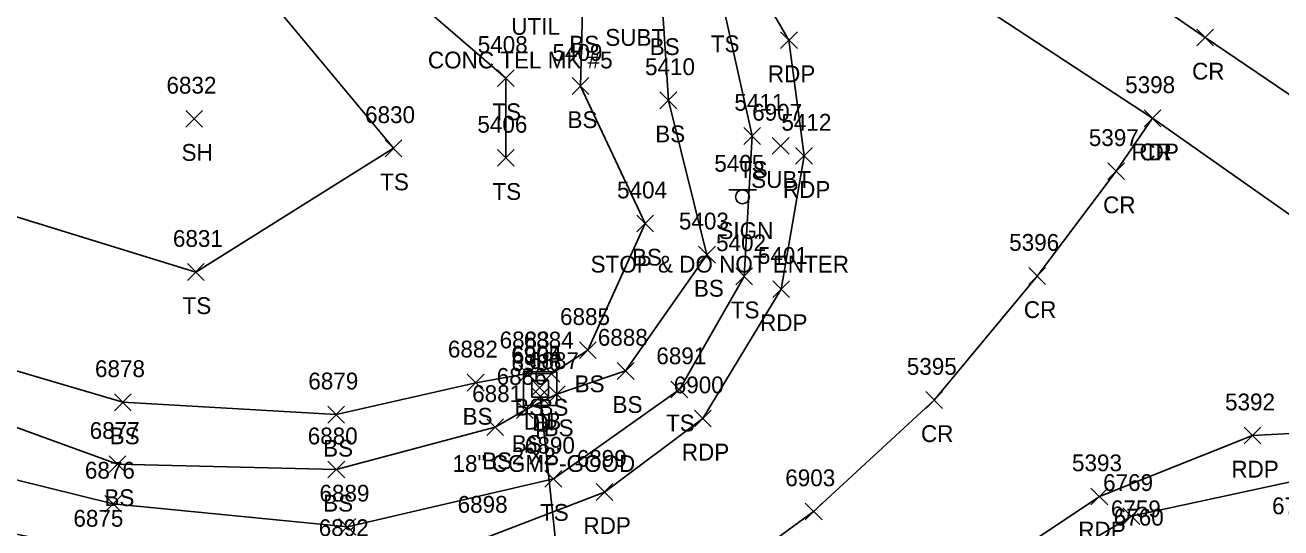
# Model space of a CAD drawing. Extents: x 1505656 to 1508446, y 700805 to 703031.
# Drawn here: x 1507471 to 1507620.5, y 701297.3 to 701357.2 of the extents above; entities that cross this region are included whole.
import ezdxf

# ---------------------------------------------------------------- set-up
doc = ezdxf.new("R2010")
doc.units = 0
for name, color, linetype in [('D_A', 7, 'Continuous'), ('D_C', 7, 'Continuous'), ('D_I', 7, 'Continuous'), ('D_TIC', 7, 'Continuous'), ('DCP', 7, 'Continuous'), ('DS', 7, 'Continuous'), ('L_A', 7, 'Continuous'), ('L_I', 7, 'Continuous'), ('L_TIC', 7, 'Continuous'), ('LELB', 7, 'Continuous'), ('P_A', 7, 'Continuous'), ('P_I', 7, 'Continuous'), ('P_TIC', 7, 'Continuous'), ('PET', 7, 'Continuous'), ('PRC', 7, 'Continuous'), ('S_A', 7, 'Continuous'), ('S_C', 7, 'Continuous'), ('S_I', 7, 'Continuous'), ('SSGN', 7, 'Continuous'), ('U_A', 7, 'Continuous'), ('U_C', 7, 'Continuous'), ('U_I', 7, 'Continuous'), ('U_TIC', 7, 'Continuous')]:
    doc.layers.add(name, color=color, linetype=linetype)

msp = doc.modelspace()

# ---------------------------------------------------------------- linework, layer by layer
at = {"layer": 'D_TIC'}
for points in [[(1507531.3, 701313.03), (1507533.3, 701315.03)], [(1507533.3, 701313.03), (1507531.3, 701315.03)], [(1507531.37, 701312), (1507533.37, 701314)], [(1507533.37, 701312), (1507531.37, 701314)]]:
    msp.add_lwpolyline(points, dxfattribs=at)
at = {"layer": 'DCP'}
msp.add_lwpolyline([(1507541.19, 701229.88), (1507532.37, 701313)], dxfattribs=at)
at = {"layer": 'DS'}
for p, q in [((1507530.36, 701315.9), (1507534.36, 701315.9)), ((1507530.36, 701311.9), (1507530.36, 701315.9)), ((1507531.36, 701312.9), (1507531.36, 701314.9)), ((1507531.36, 701314.9), (1507533.36, 701314.9)), ((1507533.36, 701314.9), (1507533.36, 701312.9)), ((1507534.36, 701315.9), (1507534.36, 701311.9)), ((1507532.37, 701313.9), (1507532.37, 701313.9)), ((1507532.37, 701313.9), (1507532.37, 701313.9)), ((1507534.36, 701311.9), (1507530.36, 701311.9)), ((1507533.36, 701312.9), (1507531.36, 701312.9))]:
    msp.add_line(p, q, dxfattribs=at)
at = {"layer": 'L_TIC'}
for points in [[(1507527.26, 701349.87), (1507529.26, 701351.87)], [(1507529.26, 701349.87), (1507527.26, 701351.87)], [(1507536.16, 701348.93), (1507538.16, 701350.93)], [(1507538.16, 701348.93), (1507536.16, 701350.93)], [(1507546.62, 701347.23), (1507548.62, 701349.23)], [(1507548.62, 701347.23), (1507546.62, 701349.23)], [(1507490.17, 701345.03), (1507492.17, 701347.03)], [(1507492.17, 701345.03), (1507490.17, 701347.03)], [(1507556.61, 701342.99), (1507558.61, 701344.99)], [(1507558.61, 701342.99), (1507556.61, 701344.99)], [(1507513.9, 701341.52), (1507515.9, 701343.52)], [(1507515.9, 701341.52), (1507513.9, 701343.52)], [(1507527.27, 701340.38), (1507529.27, 701342.38)], [(1507529.27, 701340.38), (1507527.27, 701342.38)], [(1507543.85, 701332.56), (1507545.85, 701334.56)], [(1507545.85, 701332.56), (1507543.85, 701334.56)], [(1507551.22, 701328.86), (1507553.22, 701330.86)], [(1507553.22, 701328.86), (1507551.22, 701330.86)], [(1507490.37, 701326.79), (1507492.37, 701328.79)], [(1507492.37, 701326.79), (1507490.37, 701328.79)], [(1507555.64, 701326.28), (1507557.64, 701328.28)], [(1507557.64, 701326.28), (1507555.64, 701328.28)], [(1507537.02, 701317.49), (1507539.02, 701319.49)], [(1507539.02, 701317.49), (1507537.02, 701319.49)], [(1507529.84, 701314.71), (1507531.84, 701316.71)], [(1507531.84, 701314.71), (1507529.84, 701316.71)], [(1507532.71, 701314.69), (1507534.71, 701316.69)], [(1507534.71, 701314.69), (1507532.71, 701316.69)], [(1507541.53, 701315.02), (1507543.53, 701317.02)], [(1507543.53, 701315.02), (1507541.53, 701317.02)], [(1507523.68, 701313.62), (1507525.68, 701315.62)], [(1507525.68, 701313.62), (1507523.68, 701315.62)], [(1507547.93, 701312.82), (1507549.93, 701314.82)], [(1507549.93, 701312.82), (1507547.93, 701314.82)], [(1507481.66, 701311.29), (1507483.66, 701313.29)], [(1507483.66, 701311.29), (1507481.66, 701313.29)], [(1507533.33, 701312.25), (1507535.33, 701314.25)], [(1507535.33, 701312.25), (1507533.33, 701314.25)], [(1507507.07, 701309.82), (1507509.07, 701311.82)], [(1507509.07, 701309.82), (1507507.07, 701311.82)], [(1507529.54, 701310.37), (1507531.54, 701312.37)], [(1507531.54, 701310.37), (1507529.54, 701312.37)], [(1507526, 701308.32), (1507528, 701310.32)], [(1507528, 701308.32), (1507526, 701310.32)], [(1507481.03, 701303.93), (1507483.03, 701305.93)], [(1507483.03, 701303.93), (1507481.03, 701305.93)], [(1507507.08, 701303.28), (1507509.08, 701305.28)], [(1507509.08, 701303.28), (1507507.08, 701305.28)], [(1507532.93, 701302.18), (1507534.93, 701304.18)], [(1507534.93, 701302.18), (1507532.93, 701304.18)], [(1507480.51, 701299.2), (1507482.51, 701301.2)], [(1507482.51, 701299.2), (1507480.51, 701301.2)], [(1507601.75, 701297.73), (1507603.75, 701299.73)], [(1507603.75, 701297.73), (1507601.75, 701299.73)], [(1507508.4, 701296.47), (1507510.4, 701298.47)], [(1507510.4, 701296.47), (1507508.4, 701298.47)]]:
    msp.add_lwpolyline(points, dxfattribs=at)
at = {"layer": 'LELB'}
for points in [[(1507556.64, 701327.28), (1507557.61, 701343.99), (1507554.26, 701358.96), (1507537.42, 701375.15), (1507498.82, 701402.26), (1507464.49, 701426.4), (1507427.31, 701449.55), (1507406.66, 701464.53), (1507384.23, 701478.08), (1507360.68, 701483.28)], [(1507552.22, 701329.86), (1507547.62, 701348.23), (1507546.96, 701358.62), (1507528.89, 701372.8), (1507497.02, 701400), (1507459.73, 701419.9), (1507423.54, 701446.06), (1507404.35, 701459.25), (1507380.55, 701473.13), (1507356.78, 701473.15)], [(1507544.85, 701333.56), (1507537.16, 701349.93), (1507537.38, 701358.92), (1507523.47, 701367.02), (1507491.66, 701393.21), (1507456.99, 701414.76), (1507421.42, 701443.41), (1507407.61, 701451.12), (1507389.23, 701462.81)], [(1507244.77, 701449.89), (1507281.83, 701431.77), (1507306.24, 701422.98), (1507349.34, 701422.75), (1507389.23, 701429.14), (1507420.95, 701414.98), (1507446.82, 701397.27), (1507479.15, 701378.11), (1507493.85, 701367.81), (1507514.9, 701342.52), (1507491.37, 701327.79), (1507458.66, 701337.87), (1507423.97, 701348.78), (1507386.76, 701365.39), (1507354.41, 701381.26)], [(1507235.56, 701433.65), (1507276.85, 701410.17), (1507315.69, 701384.08), (1507347.33, 701367.45), (1507378.23, 701346.54), (1507406.05, 701333.56), (1507432.55, 701320.24), (1507465.52, 701310.91), (1507482.03, 701304.93), (1507508.08, 701304.28), (1507527, 701309.32), (1507530.54, 701311.37), (1507534.33, 701313.25), (1507542.53, 701316.02)], [(1507233.42, 701430.73), (1507274.38, 701405.85), (1507313.77, 701380.88), (1507345.78, 701364.01), (1507376.65, 701344.28), (1507403.21, 701328.51), (1507429.39, 701315.22), (1507462.05, 701305), (1507481.51, 701300.2), (1507509.4, 701297.47), (1507533.93, 701303.18), (1507548.93, 701313.82)], [(1507276.85, 701410.17), (1507314.61, 701390.89), (1507350.47, 701373.21), (1507382.29, 701350.94), (1507409.06, 701339.05), (1507436.21, 701326.88), (1507468.39, 701316.49), (1507482.66, 701312.29), (1507508.07, 701310.82), (1507524.68, 701314.62), (1507530.84, 701315.71), (1507533.71, 701315.69), (1507538.02, 701318.49)], [(1507528.27, 701341.38), (1507528.26, 701350.87), (1507511.97, 701364.96), (1507483.22, 701384.55), (1507451.58, 701403.84)], [(1507664.64, 701288.76), (1507647.23, 701299.02), (1507624.46, 701303.4), (1507602.75, 701298.73), (1507589.52, 701290.79), (1507567.73, 701274.99), (1507546.1, 701263.56), (1507532.57, 701260.5), (1507511.15, 701257.25), (1507494.82, 701257.14), (1507477.93, 701258.45), (1507454.88, 701263), (1507442.63, 701266.73), (1507416.76, 701276.5), (1507380.5, 701295.43), (1507349.66, 701313.74), (1507307.1, 701338.01), (1507263.23, 701366.42), (1507214.44, 701398.2)], [(1507538.02, 701318.49), (1507544.85, 701333.56)], [(1507542.53, 701316.02), (1507552.22, 701329.86)], [(1507548.93, 701313.82), (1507556.64, 701327.28)]]:
    msp.add_lwpolyline(points, dxfattribs=at)
at = {"layer": 'P_TIC'}
for points in [[(1507560.98, 701354.39), (1507562.98, 701356.39)], [(1507562.98, 701354.39), (1507560.98, 701356.39)], [(1507610.54, 701354.7), (1507612.54, 701356.7)], [(1507612.54, 701354.7), (1507610.54, 701356.7)], [(1507604.27, 701345.09), (1507606.27, 701347.09)], [(1507606.27, 701345.09), (1507604.27, 701347.09)], [(1507604.27, 701345.09), (1507606.27, 701347.09)], [(1507606.27, 701345.09), (1507604.27, 701347.09)], [(1507562.77, 701340.62), (1507564.77, 701342.62)], [(1507564.77, 701340.62), (1507562.77, 701342.62)], [(1507599.94, 701338.79), (1507601.94, 701340.79)], [(1507601.94, 701338.79), (1507599.94, 701340.79)], [(1507590.52, 701326.32), (1507592.52, 701328.32)], [(1507592.52, 701326.32), (1507590.52, 701328.32)], [(1507560.05, 701324.76), (1507562.05, 701326.76)], [(1507562.05, 701324.76), (1507560.05, 701326.76)], [(1507578.27, 701311.56), (1507580.27, 701313.56)], [(1507580.27, 701311.56), (1507578.27, 701313.56)], [(1507550.73, 701309.36), (1507552.73, 701311.36)], [(1507552.73, 701309.36), (1507550.73, 701311.36)], [(1507616.16, 701307.33), (1507618.16, 701309.33)], [(1507618.16, 701307.33), (1507616.16, 701309.33)], [(1507539.02, 701300.61), (1507541.02, 701302.61)], [(1507541.02, 701300.61), (1507539.02, 701302.61)], [(1507597.94, 701300.08), (1507599.94, 701302.08)], [(1507599.94, 701300.08), (1507597.94, 701302.08)], [(1507563.92, 701298.3), (1507565.92, 701300.3)], [(1507565.92, 701298.3), (1507563.92, 701300.3)]]:
    msp.add_lwpolyline(points, dxfattribs=at)
at = {"layer": 'PET'}
for points in [[(1507650.58, 701314.23), (1507605.27, 701346.09), (1507547.72, 701383.86), (1507511.59, 701409.01), (1507468.93, 701438.18), (1507436.61, 701460.37), (1507397.2, 701486.89), (1507374.7, 701502.05)], [(1507231.61, 701427.39), (1507272.91, 701402.71), (1507311.8, 701378.29), (1507343.21, 701359.04), (1507374.88, 701340.26), (1507401.32, 701325.13), (1507427.17, 701310.75), (1507459.87, 701298.7), (1507480.09, 701294.48), (1507509.29, 701293.36), (1507525.83, 701296.14), (1507540.02, 701301.61), (1507551.73, 701310.36)], [(1507561.05, 701325.76), (1507563.77, 701341.62), (1507561.98, 701355.39), (1507555.88, 701365.81), (1507544.33, 701378.59)], [(1507551.73, 701310.36), (1507561.05, 701325.76)], [(1507643.95, 701304.95), (1507633.79, 701309.2), (1507617.16, 701308.33), (1507598.94, 701301.08)], [(1507573.81, 701284.3), (1507598.94, 701301.08)]]:
    msp.add_lwpolyline(points, dxfattribs=at)
at = {"layer": 'PRC'}
for points in [[(1507656.71, 701325.12), (1507611.54, 701355.7), (1507570.54, 701383.97), (1507541.91, 701403.48), (1507511.11, 701424.43), (1507476, 701448.42), (1507444.02, 701470.19), (1507404.16, 701496.97), (1507381.62, 701512.17)], [(1507224.48, 701413.97), (1507267.93, 701386.51), (1507302.71, 701364.98), (1507334.78, 701345.63), (1507366.2, 701326.16), (1507393.17, 701310.52), (1507419.83, 701295.27), (1507450.97, 701283.62), (1507477.64, 701277.69), (1507509.18, 701276.82), (1507530.27, 701280.07), (1507548.96, 701287.59), (1507564.92, 701299.3)], [(1507579.27, 701312.56), (1507591.52, 701327.32), (1507600.94, 701339.79), (1507605.27, 701346.09)], [(1507564.92, 701299.3), (1507579.27, 701312.56)]]:
    msp.add_lwpolyline(points, dxfattribs=at)
at = {"layer": 'SSGN'}
for p, q in [((1507554.8, 701337.58), (1507558.13, 701337.58)), ((1507556.45, 701336.75), (1507556.45, 701336.75))]:
    msp.add_line(p, q, dxfattribs=at)
msp.add_circle((1507556.45, 701336.75), 0.833, dxfattribs=at)
at = {"layer": 'U_TIC'}
for points in [[(1507559.99, 701341.81), (1507561.99, 701343.81)], [(1507561.99, 701341.81), (1507559.99, 701343.81)]]:
    msp.add_lwpolyline(points, dxfattribs=at)

# ---------------------------------------------------------------- texts
at = {"layer": 'D_A'}
for s, p in [('DIB', (1507530.4, 701309.03)), ('DI', (1507531.42, 701308.9)), ('P', (1507531.75, 701308))]:
    msp.add_text(s, height=2, dxfattribs=at).set_placement(p)
at = {"layer": 'D_C'}
for s, p in [('18" CGMP-GOOD', (1507521.92, 701304)), ("2'X2'", (1507528.97, 701304.9))]:
    msp.add_text(s, height=2, dxfattribs=at).set_placement(p)
at = {"layer": 'D_I'}
for s, p in [('6905', (1507528.91, 701317.03)), ('6906', (1507528.93, 701316)), ('6904', (1507528.98, 701316.9))]:
    msp.add_text(s, height=2, dxfattribs=at).set_placement(p)
at = {"layer": 'L_A'}
for s, p in [('BS', (1507535.82, 701353.92)), ('BS', (1507545.4, 701353.62)), ('TS', (1507552.67, 701353.96)), ('TS', (1507526.67, 701345.87)), ('BS', (1507535.61, 701344.93)), ('BS', (1507546.06, 701343.23)), ('SH', (1507489.66, 701341.03)), ('TS', (1507556.02, 701338.99)), ('TS', (1507513.31, 701337.52)), ('TS', (1507526.68, 701336.38)), ('BS', (1507543.29, 701328.56)), ('BS', (1507550.66, 701324.86)), ('TS', (1507489.78, 701322.79)), ('TS', (1507555.05, 701322.28)), ('BS', (1507536.46, 701313.49)), ('BS', (1507540.97, 701311.02)), ('BS', (1507523.12, 701309.62)), ('BS', (1507529.28, 701310.71)), ('BS', (1507532.15, 701310.69)), ('BS', (1507532.77, 701308.25)), ('TS', (1507547.34, 701308.82)), ('BS', (1507481.1, 701307.29)), ('BS', (1507506.51, 701305.82)), ('BS', (1507528.98, 701306.37)), ('BS', (1507525.44, 701304.32)), ('BS', (1507480.47, 701299.93)), ('BS', (1507506.52, 701299.28)), ('TS', (1507532.34, 701298.18))]:
    msp.add_text(s, height=2, dxfattribs=at).set_placement(p)
at = {"layer": 'L_I'}
for s, p in [('5408', (1507524.92, 701353.87)), ('5409', (1507533.82, 701352.93)), ('5410', (1507544.84, 701351.23)), ('6832', (1507487.86, 701349.03)), ('5411', (1507555.48, 701346.99)), ('6830', (1507511.51, 701345.52)), ('5406', (1507524.88, 701344.38)), ('5404', (1507541.51, 701336.56)), ('5403', (1507548.88, 701332.86)), ('6831', (1507488.63, 701330.79)), ('5402', (1507553.3, 701330.28)), ('6885', (1507534.72, 701321.49)), ('6883', (1507527.53, 701318.71)), ('6884', (1507530.4, 701318.69)), ('6888', (1507539.22, 701319.02)), ('6882', (1507521.37, 701317.62)), ('6887', (1507531.02, 701316.25)), ('6891', (1507546.19, 701316.82)), ('6878', (1507479.35, 701315.29)), ('6886', (1507527.18, 701314.37)), ('6879', (1507504.75, 701313.82)), ('6881', (1507524.26, 701312.32)), ('6877', (1507478.72, 701307.93)), ('6880', (1507504.68, 701307.28)), ('6890', (1507530.54, 701306.18)), ('6876', (1507478.15, 701303.2)), ('6769', (1507599.38, 701301.73)), ('6889', (1507506.08, 701300.47)), ('6760', (1507600.65, 701297.61)), ('6761', (1507619.5, 701298.96))]:
    msp.add_text(s, height=2, dxfattribs=at).set_placement(p)
at = {"layer": 'P_A'}
for s, p in [('RDP', (1507559.47, 701350.39)), ('CR', (1507609.97, 701350.7)), ('RDP', (1507602.76, 701341.09)), ('CR', (1507603.7, 701341.09)), ('RDP', (1507561.26, 701336.62)), ('CR', (1507599.38, 701334.79)), ('CR', (1507589.95, 701322.32)), ('RDP', (1507558.54, 701320.76)), ('CR', (1507577.7, 701307.56)), ('RDP', (1507549.22, 701305.36)), ('RDP', (1507614.65, 701303.33)), ('RDP', (1507537.51, 701296.61)), ('RDP', (1507596.43, 701296.08))]:
    msp.add_text(s, height=2, dxfattribs=at).set_placement(p)
at = {"layer": 'P_I'}
for s, p in [('5398', (1507602.01, 701349.09)), ('5398', (1507602.01, 701349.09)), ('5412', (1507561.08, 701344.62)), ('5397', (1507597.68, 701342.79)), ('5396', (1507588.2, 701330.32)), ('5401', (1507558.28, 701328.76)), ('5395', (1507576.01, 701315.56)), ('6900', (1507548.26, 701313.36)), ('5392', (1507613.9, 701311.33)), ('6899', (1507536.71, 701304.61)), ('5393', (1507595.68, 701304.08)), ('6903', (1507561.54, 701302.3)), ('6898', (1507522.53, 701299.14)), ('6875', (1507476.78, 701297.48)), ('6892', (1507505.99, 701296.36))]:
    msp.add_text(s, height=2, dxfattribs=at).set_placement(p)
at = {"layer": 'S_A'}
msp.add_text('SIGN', height=2, dxfattribs=at).set_placement((1507553.58, 701331.73))
at = {"layer": 'S_C'}
msp.add_text('STOP & DO NOT ENTER', height=2, dxfattribs=at).set_placement((1507538.36, 701327.73))
at = {"layer": 'S_I'}
for s, p in [('5405', (1507553.09, 701339.73)), ('6759', (1507600.31, 701298.61))]:
    msp.add_text(s, height=2, dxfattribs=at).set_placement(p)
at = {"layer": 'U_A'}
for s, p in [('UTIL', (1507528.92, 701356.03)), ('SUBT', (1507540.11, 701354.72)), ('SUBT', (1507557.48, 701337.81))]:
    msp.add_text(s, height=2, dxfattribs=at).set_placement(p)
at = {"layer": 'U_C'}
msp.add_text('CONC TEL MK #5', height=2, dxfattribs=at).set_placement((1507518.99, 701352.03))
at = {"layer": 'U_I'}
msp.add_text('6907', height=2, dxfattribs=at).set_placement((1507557.6, 701345.81))

doc.saveas('drawing.dxf')
